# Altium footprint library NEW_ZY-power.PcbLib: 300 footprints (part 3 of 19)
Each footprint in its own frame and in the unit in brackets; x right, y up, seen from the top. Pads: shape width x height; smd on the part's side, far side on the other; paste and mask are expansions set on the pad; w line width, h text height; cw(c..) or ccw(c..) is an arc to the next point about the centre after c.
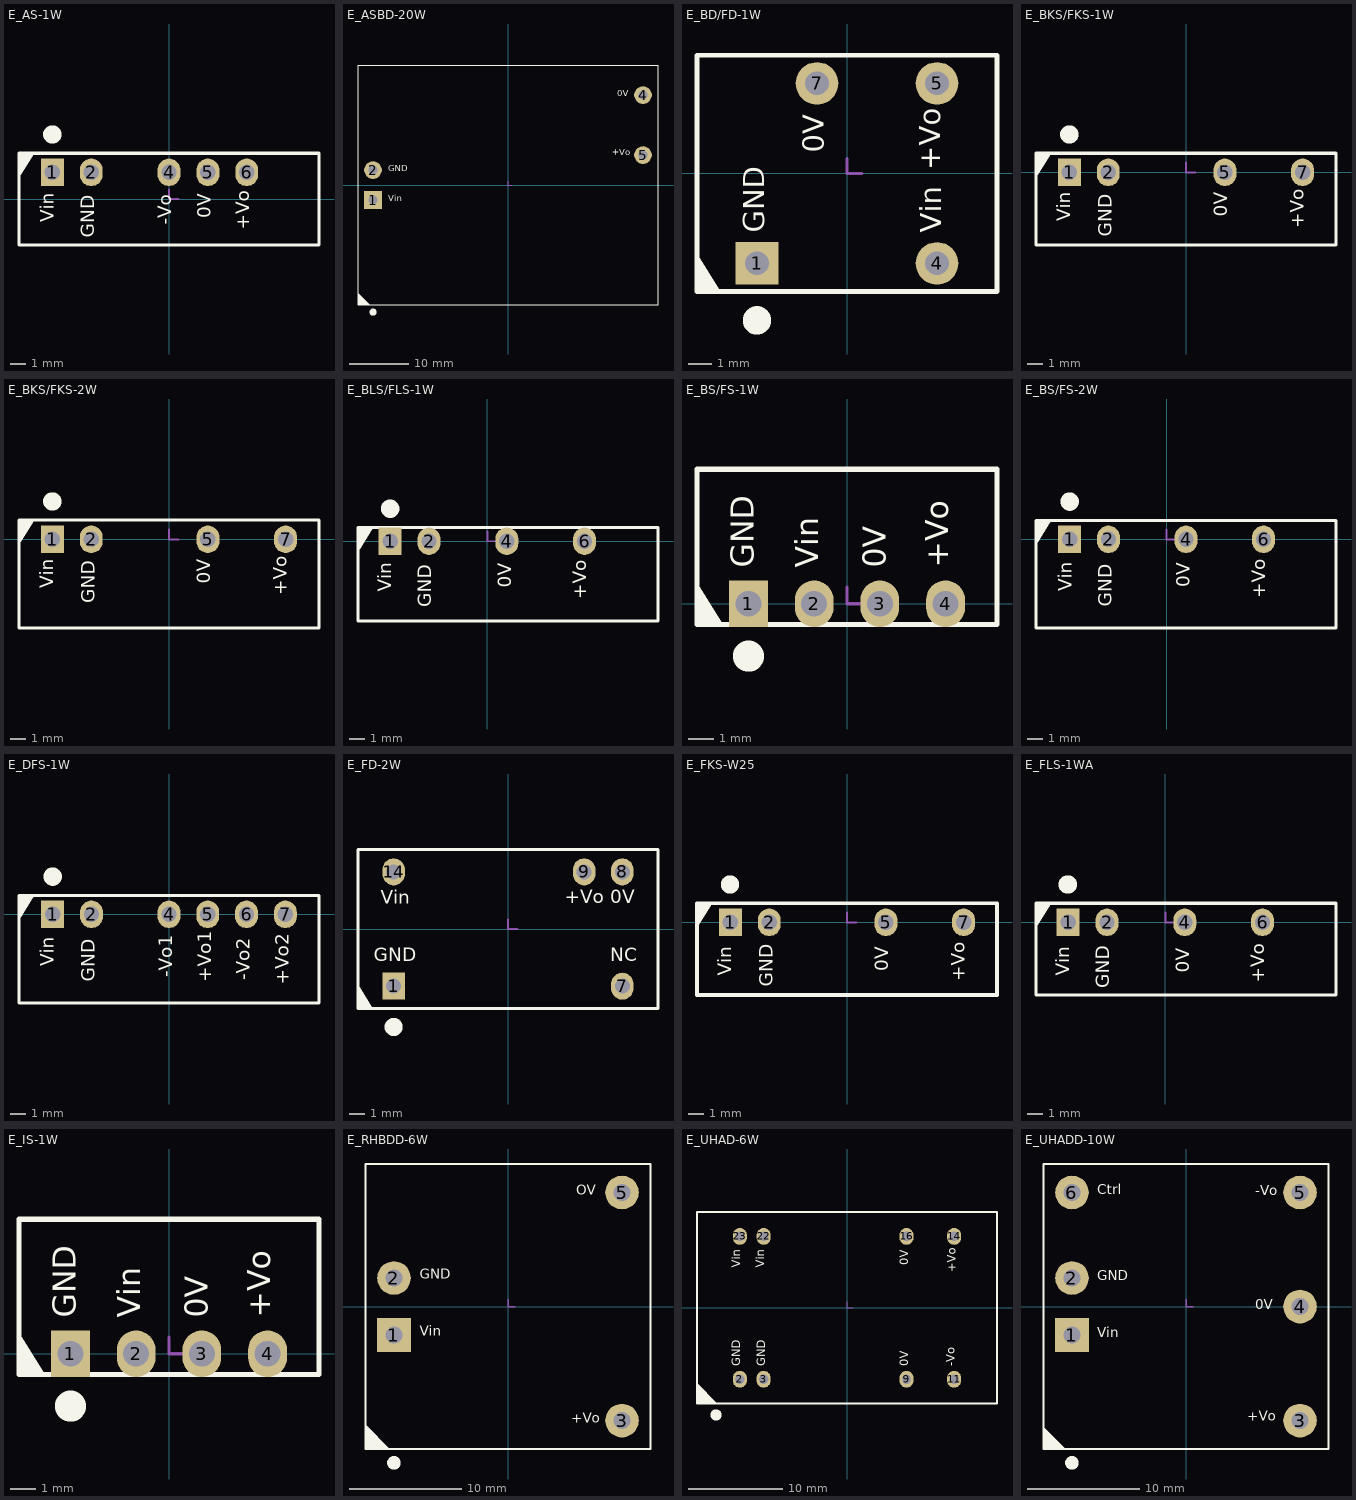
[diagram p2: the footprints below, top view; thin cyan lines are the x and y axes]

## E_AS-1W [mm]
height 10.1
pads (5):
  rect 1.5x1.8 hole 1: 1(-7.62,1.75)
  oval 1.5x1.8 hole 1: 2(-5.08,1.75) 4(0,1.75) 5(2.54,1.75) 6(5.08,1.75)
Top Overlay:
  circle w1: c-7.62,4.225 r0.1
  region: -9.8,1.414 -9.8,3 -8.806,3
  lines w0.2: -9.8,-3 -9.8,3 9.8,3 9.8,-3 -9.8,-3
  text "Vin" at -7.225,-1.521 h1.52
  text "GND" at -4.575,-2.531 h1.52
  text "-Vo" at 0.45,-1.677 h1.52
  text "0V" at 3.013,-1.249 h1.52
  text "+Vo" at 5.55,-1.989 h1.52
Mechanical 15:
  lines w0.127: 0,0.635 0,0 0.635,0

## E_ASBD-20W [mm]
height 13.8
pads (4):
  rect 3x3 hole 1.5: 1(-22.86,-2.54)
  round 3 hole 1.5: 2(-22.86,2.54) 4(22.86,15.24) 5(22.86,5.08)
Top Overlay:
  circle w1: c-22.86,-21.525 r0.1
  region: -25.4,-20.3 -23.425,-20.3 -25.4,-18.325
  lines w0.2: -25.4,-20.3 -25.4,20.3 25.4,20.3 25.4,-20.3 -25.4,-20.3
  text "GND" at -20.32,2.034 h1.78
  text "Vin" at -20.32,-3.046 h1.78
  text "+Vo" at 17.653,4.699 h1.78
  text "0V" at 18.517,14.732 h1.78
Mechanical 15:
  lines w0.127: 0,0.635 0,0 0.635,0

## E_BD/FD-1W [mm]
height 7.7
pads (4):
  rect 1.8x1.8 hole 1: 1(-3.81,-3.81)
  round 1.8 hole 1: 4(3.81,-3.81) 5(3.81,3.81) 7(-1.27,3.81)
Top Overlay:
  circle w1: c-3.81,-6.225 r0.1
  region: -6.35,-3.414 -6.35,-5 -5.356,-5
  lines w0.2: -6.35,-5 6.35,-5 6.35,5 -6.35,5 -6.35,-5
  text "GND" at -3.2,-2.516 h1.52
  text "Vin" at 4.293,-2.515 h1.52
  text "+Vo" at 4.244,0.124 h1.52
  text "0V" at -0.686,0.864 h1.52
Mechanical 15:
  lines w0.127: 0,0.635 0,0 0.635,0

## E_BKS/FKS-1W [mm]
height 10
pads (4):
  rect 1.5x1.8 hole 1: 1(-7.62,0)
  oval 1.5x1.8 hole 1: 2(-5.08,0) 5(2.54,0) 7(7.62,0)
Top Overlay:
  circle w1: c-7.62,2.475 r0.1
  region: -9.8,-0.336 -9.8,1.25 -8.806,1.25
  lines w0.2: -9.8,-4.75 9.8,-4.75 9.8,1.25 -9.8,1.25 -9.8,-4.75
  text "Vin" at -7.275,-3.181 h1.52
  text "GND" at -4.572,-4.191 h1.52
  text "0V" at 3,-2.909 h1.52
  text "+Vo" at 8,-3.649 h1.52
Mechanical 15:
  lines w0.127: 0,0.635 0,0 0.635,0

## E_BKS/FKS-2W [mm]
height 10
pads (4):
  rect 1.5x1.8 hole 1: 1(-7.62,0)
  oval 1.5x1.8 hole 1: 2(-5.08,0) 5(2.54,0) 7(7.62,0)
Top Overlay:
  circle w1: c-7.62,2.475 r0.1
  region: -9.8,-0.336 -9.8,1.25 -8.806,1.25
  lines w0.2: -9.8,-5.8 -9.8,1.25 9.8,1.25 9.8,-5.8 -9.8,-5.8
  text "Vin" at -7.275,-3.181 h1.52
  text "GND" at -4.572,-4.191 h1.52
  text "0V" at 3,-2.909 h1.52
  text "+Vo" at 8,-3.649 h1.52
Mechanical 15:
  lines w0.127: 0,0.635 0,0 0.635,0

## E_BLS/FLS-1W [mm]
height 10
pads (4):
  rect 1.5x1.8 hole 1: 1(-6.35,0)
  oval 1.5x1.8 hole 1: 2(-3.81,0) 4(1.27,0) 6(6.35,0)
Top Overlay:
  circle w1: c-6.35,2.125 r0.1
  region: -8.45,-0.686 -8.45,0.9 -7.456,0.9
  lines w0.2: -8.45,-5.2 11.15,-5.2 11.15,0.9 -8.45,0.9 -8.45,-5.2
  text "Vin" at -5.969,-3.308 h1.52
  text "GND" at -3.378,-4.318 h1.52
  text "0V" at 1.854,-3.036 h1.52
  text "+Vo" at 6.756,-3.776 h1.52
Mechanical 15:
  lines w0.127: 0,0.635 0,0 0.635,0

## E_BS/FS-1W [mm]
height 10.1
pads (4):
  rect 1.5x1.8 hole 1: 1(-3.81,0)
  oval 1.5x1.8 hole 1: 2(-1.27,0) 3(1.27,0) 4(3.81,0)
Top Overlay:
  circle w1: c-3.81,-2.025 r0.1
  region: -5.8,0.786 -5.8,-0.8 -4.806,-0.8
  lines w0.2: 2.045,-0.8 4.636,-0.8 5.8,-0.8 ; 5.8,-0.8 5.8,5.2 -5.8,5.2 -5.8,-0.8 5.8,-0.8
  text "GND" at -3.315,1.396 h1.52
  text "Vin" at -0.826,1.397 h1.52
  text "0V" at 1.791,1.396 h1.52
  text "+Vo" at 4.204,1.396 h1.52
Mechanical 15:
  lines w0.127: 0,0.635 0,0 0.635,0

## E_BS/FS-2W [mm]
height 10.1
pads (4):
  rect 1.5x1.8 hole 1: 1(-6.35,0)
  oval 1.5x1.8 hole 1: 2(-3.81,0) 4(1.27,0) 6(6.35,0)
Top Overlay:
  circle w1: c-6.35,2.475 r0.1
  region: -8.555,-0.336 -8.555,1.25 -7.561,1.25
  lines w0.2: -8.555,-5.8 -8.555,1.25 11.095,1.25 11.095,-5.8 -8.555,-5.8
  text "+Vo" at 6.745,-3.866 h1.52
  text "0V" at 1.795,-3.126 h1.52
  text "GND" at -3.302,-4.408 h1.52
  text "Vin" at -5.93,-3.398 h1.52
Mechanical 15:
  lines w0.127: 0,0.635 0,0 0.635,0

## E_DFS-1W [mm]
height 10.1
pads (6):
  rect 1.5x1.8 hole 1: 1(-7.62,0)
  oval 1.5x1.8 hole 1: 2(-5.08,0) 4(0,0) 5(2.54,0) 6(5.08,0) 7(7.62,0)
Top Overlay:
  circle w1: c-7.62,2.475 r0.1
  region: -9.825,-0.336 -9.825,1.25 -8.831,1.25
  lines w0.2: -9.825,-5.8 -9.825,1.25 9.825,1.25 9.825,-5.8 -9.825,-5.8
  text "-Vo1" at 0.508,-4.128 h1.52
  text "Vin" at -7.239,-3.414 h1.52
  text "GND" at -4.572,-4.424 h1.52
  text "+Vo1" at 3.048,-4.44 h1.52
  text "-Vo2" at 5.588,-4.307 h1.52
  text "+Vo2" at 8.128,-4.619 h1.52

## E_FD-2W [mm]
height 8.1
pads (5):
  rect 1.5x1.8 hole 1 paste-0.787: 1(-7.62,-3.81)
  oval 1.5x1.8 hole 1 paste-0.787: 7(7.62,-3.81) 8(7.62,3.81) 9(5.08,3.81) 14(-7.62,3.81)
Top Overlay:
  circle w1: c-7.62,-6.525 r0.1
  region: -10,-3.714 -10,-5.3 -9.006,-5.3
  lines w0.2: -10,-5.3 -10,5.3 10,5.3 10,-5.3 -10,-5.3
  text "NC" at 6.807,-2.438 h1.52
  text "0V" at 6.807,1.422 h1.52
  text "+Vo" at 3.785,1.422 h1.52
  text "Vin" at -8.484,1.397 h1.52
  text "GND" at -8.941,-2.438 h1.52
Mechanical 15:
  lines w0.127: 0,0.635 0,0 0.635,0

## E_FKS-W25 [mm]
height 10.1
pads (4):
  rect 1.5x1.8 hole 1: 1(-7.62,0)
  oval 1.5x1.8 hole 1: 2(-5.08,0) 5(2.54,0) 7(7.62,0)
Top Overlay:
  circle w1: c-7.644,2.475 r0.1
  region: -9.8,-0.336 -9.8,1.25 -8.806,1.25
  lines w0.254: -9.8,-4.75 9.8,-4.75 9.8,1.25 -9.8,1.25 -9.8,-4.75
  text "Vin" at -7.275,-3.475 h1.52
  text "GND" at -4.572,-4.191 h1.52
  text "0V" at 3,-3.196 h1.52
  text "+Vo" at 8,-3.85 h1.52
Mechanical 15:
  lines w0.127: 0,0.635 0,0 0.635,0

## E_FLS-1WA [mm]
height 10.1
pads (4):
  rect 1.5x1.8 hole 1: 1(-6.35,0)
  oval 1.5x1.8 hole 1: 2(-3.81,0) 4(1.27,0) 6(6.35,0)
Top Overlay:
  circle w1: c-6.374,2.475 r0.1
  region: -8.45,-0.336 -8.45,1.25 -7.456,1.25
  lines w0.2: -8.45,-4.75 11.15,-4.75 11.15,1.25 -8.45,1.25 -8.45,-4.75
  text "+Vo" at 6.756,-3.937 h1.52
  text "0V" at 1.854,-3.302 h1.52
  text "GND" at -3.378,-4.318 h1.52
  text "Vin" at -5.969,-3.48 h1.52
Mechanical 15:
  lines w0.127: 0,0.635 0,0 0.635,0

## E_IS-1W [mm]
height 6
pads (4):
  rect 1.5x1.8 hole 1: 1(-3.81,0)
  oval 1.5x1.8 hole 1: 2(-1.27,0) 3(1.27,0) 4(3.81,0)
Top Overlay:
  circle w1: c-3.81,-2.025 r0.1
  region: -5.8,0.786 -5.8,-0.8 -4.806,-0.8
  lines w0.2: 2.045,-0.8 4.636,-0.8 5.8,-0.8 ; 5.8,-0.8 -5.8,-0.8 -5.8,5.2 5.8,5.2 5.8,-0.8
  text "+Vo" at 4.204,1.396 h1.52
  text "0V" at 1.791,1.396 h1.52
  text "Vin" at -0.826,1.397 h1.52
  text "GND" at -3.315,1.396 h1.52
Mechanical 15:
  lines w0.127: 0,0.635 0,0 0.635,0

## E_RHBDD-6W [mm]
height 11.7
pads (4):
  rect 3x3 hole 1.5: 1(-10.16,-2.54)
  round 3 hole 1.5: 2(-10.16,2.54) 3(10.16,-10.16) 5(10.16,10.16)
Top Overlay:
  circle w1: c-10.16,-13.925 r0.1
  region: -12.598,-12.603 -10.623,-12.603 -12.598,-10.628
  lines w0.2: -12.7,-12.7 -12.7,12.7 12.7,12.7 12.7,-12.7 -12.7,-12.7
  text "Vin" at -7.873,-2.921 h1.52
  text "GND" at -7.874,2.159 h1.52
  text "OV" at 6.096,9.652 h1.52
  text "+Vo" at 5.649,-10.668 h1.52
Mechanical 15:
  lines w0.127: 0,0.635 0,0 0.635,0

## E_UHAD-6W [mm]
height 11
pads (8):
  oval 1.5x1.8 hole 1: 2(-11.43,-7.62) 3(-8.89,-7.62) 9(6.35,-7.62) 11(11.43,-7.62) 14(11.43,7.62) 16(6.35,7.62) 22(-8.89,7.62) 23(-11.43,7.62)
Top Overlay:
  circle w1: c-13.97,-11.425 r0.1
  region: -15.898,-10.103 -13.923,-10.103 -15.898,-8.128
  lines w0.2: -16,-10.2 -16,10.2 16,10.2 16,-10.2 -16,-10.2
  text "GND" at -11.049,-6.223 h1.52
  text "GND" at -8.382,-6.223 h1.52
  text "Vin" at -11.049,4.278 h1.52
  text "Vin" at -8.509,4.278 h1.52
  text "-Vo" at 11.811,-6.223 h1.52
  text "+Vo" at 11.938,3.81 h1.52
  text "0V" at 6.858,4.55 h1.52
  text "0V" at 6.833,-6.223 h1.52
Mechanical 15:
  lines w0.127: 0,0.635 0,0 0.635,0

## E_UHADD-10W [mm]
height 11.7
pads (6):
  rect 3x3 hole 1.5: 1(-10.16,-2.54)
  round 3 hole 1.5: 2(-10.16,2.54) 3(10.16,-10.16) 4(10.16,0) 5(10.16,10.16) 6(-10.16,10.16)
Top Overlay:
  circle w1: c-10.16,-13.925 r0.1
  region: -12.7,-12.7 -10.725,-12.7 -12.7,-10.725
  lines w0.2: -12.7,-12.7 -12.7,12.7 12.7,12.7 12.7,-12.7 -12.7,-12.7
  text "0V" at 6.175,-0.535 h1.52
  text "GND" at -7.901,2.05 h1.52
  text "Vin" at -7.9,-3.025 h1.52
  text "Ctrl" at -7.901,9.7 h1.52
  text "+Vo" at 5.435,-10.5 h1.52
  text "-Vo" at 6.175,9.625 h1.52
Mechanical 15:
  lines w0.127: 0,0.635 0,0 0.635,0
